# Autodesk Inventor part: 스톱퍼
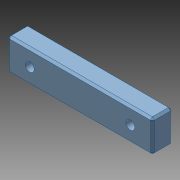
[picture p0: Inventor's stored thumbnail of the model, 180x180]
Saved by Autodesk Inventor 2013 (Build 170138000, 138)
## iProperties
Created: 2023-09
Part Number: 스톱퍼
Material: 강철, 탄소
Document SubType Name: Modeling
Designer: mdu-01
Density: 1 g/cm^3
Author: mdu-01
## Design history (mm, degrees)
sketch "스케치1"
  geometry: L1 (-36, -8)-(36, -8); L2 (36, -8)-(36, 8); L3 (36, 8)-(-36, 8); L4 (-36, 8)-(-36, -8); L5 (-36, -8)-(36, 8); L6 (36, -8)-(-36, 8); 1 further point
  constraints: 12 end point, 2 midpoint, 2 parallel, 1 horizontal, 1 perpendicular
  dimensions: "d0" = 16 distance between parallel lines of L1 L3; "d2" = 72 distance between parallel lines of L2 L4
extrude "돌출1" new body sketch "스케치1" distance "d3" = 10; taper "d4" = 0 deg
sketch "스케치2"
  geometry: L1 (0, 0)-(0, -7.829); 2 further points
  constraints: 2 end point, 1 horizontal alignment, 1 symmetric about line, 1 vertical
  dimensions: "d5" = 50 distance of point (25, 0) point (-25, 0)
hole "구멍1" sketch "스케치2" at (-25, 0), (25, 0) diameter "d7" = 4.5; stored, may be unused: countersink angle "d11" = 90 deg, drill point angle "d13" = 118 deg; dims "d8" = 6, "d9" = 8, "d10" = 4.4, "d12" = 8
chamfer "모따기1" distance "d14" = 1; stored, may be unused: second distance "d15" = 2, angle "d16" = 45 deg
node "솔리드1"
